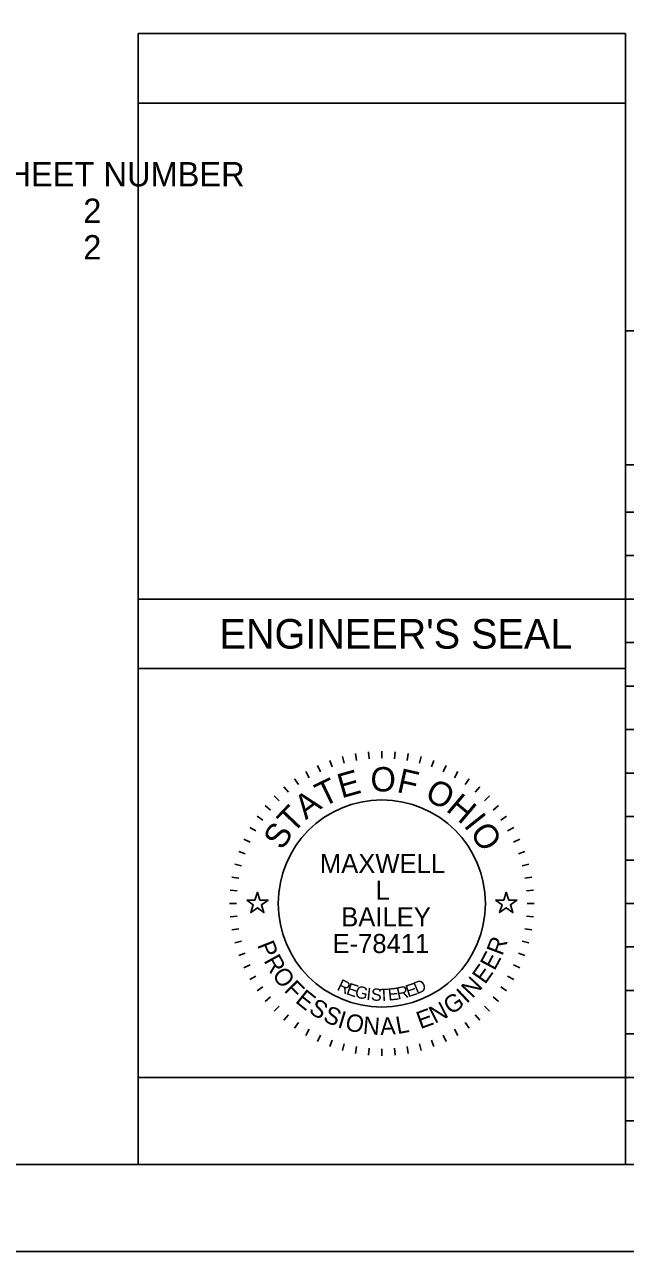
# Model space of a CAD drawing. Extents: x 0 to 34, y 0 to 22.
# Drawn here: x 6.7 to 10.15, y 0 to 7.05 of the extents above; entities that cross this region are included whole.
import ezdxf

# ---------------------------------------------------------------- set-up
doc = ezdxf.new("R2010")
doc.units = 0
for name, color, linetype in [('SH_Border', 7, 'Continuous'), ('SH_Cut_Line', 7, 'Continuous'), ('SH_Data', 7, 'Continuous'), ('SH_Seal', 7, 'Continuous'), ('SH_Text', 7, 'Continuous')]:
    doc.layers.add(name, color=color, linetype=linetype)

msp = doc.modelspace()

# ---------------------------------------------------------------- linework, layer by layer
at = {"layer": 'SH_Border'}
msp.add_lwpolyline([(1.5, 21.5), (33.5, 21.5), (33.5, 0.5), (1.5, 0.5)], close=True, dxfattribs=at)
at = {"layer": 'SH_Cut_Line'}
msp.add_lwpolyline([(0, 0), (34, 0), (34, 22), (0, 22)], close=True, dxfattribs=at)
at = {"layer": 'SH_Data'}
for p, q in [((7.35, 6.6), (10.15, 6.6)), ((10.15, 5.2917), (23.6, 5.2917)), ((10.15, 0.5), (10.15, 5.2917)), ((10.15, 4.5209), (23.6, 4.5209)), ((10.15, 4.25), (21.875, 4.25)), ((10.15, 4), (21.875, 4)), ((10.15, 3.75), (7.35, 3.75)), ((7.35, 3.75), (7.35, 0.5)), ((10.15, 3.75), (21.875, 3.75)), ((10.15, 0.5), (10.15, 3.75)), ((10.15, 3.5), (21.875, 3.5)), ((7.35, 3.35), (10.15, 3.35)), ((10.15, 3.35), (7.35, 3.35)), ((10.15, 3.25), (23.6, 3.25)), ((10.15, 3), (23.6, 3)), ((10.15, 2.75), (23.6, 2.75)), ((10.15, 2.5), (23.6, 2.5)), ((10.15, 2.25), (23.6, 2.25)), ((10.15, 2), (23.6, 2)), ((10.15, 1.75), (23.6, 1.75)), ((10.15, 1.5), (23.6, 1.5)), ((10.15, 1.25), (23.6, 1.25)), ((10.15, 1), (23.6, 1)), ((10.15, 0.75), (23.6, 0.75)), ((10.15, 0.5), (7.35, 0.5))]:
    msp.add_line(p, q, dxfattribs=at)
for points in [[(10.15, 7), (7.35, 7), (7.35, 3.75), (10.15, 3.75)], [(10.15, 3.75), (7.35, 3.75), (7.35, 0.5), (10.15, 0.5)], [(10.15, 0.5), (10.15, 1), (7.35, 1), (7.35, 0.5)]]:
    msp.add_lwpolyline(points, close=True, dxfattribs=at)
at = {"layer": 'SH_Seal'}
for p, q in [((8.4507, 2.8222), (8.4644, 2.7846)), ((8.5235, 2.8452), (8.5339, 2.8065)), ((8.5981, 2.8617), (8.605, 2.8223)), ((8.6737, 2.8717), (8.6772, 2.8318)), ((8.75, 2.875), (8.75, 2.835)), ((8.8263, 2.8717), (8.8228, 2.8318)), ((8.9019, 2.8617), (8.895, 2.8223)), ((8.9765, 2.8452), (8.9661, 2.8065)), ((9.0493, 2.8222), (9.0356, 2.7846)), ((8.3125, 2.7578), (8.3325, 2.7231)), ((8.3802, 2.793), (8.3971, 2.7568)), ((9.1198, 2.793), (9.1029, 2.7568)), ((9.1875, 2.7578), (9.1675, 2.7231)), ((8.2481, 2.7168), (8.2711, 2.684)), ((9.2519, 2.7168), (9.2289, 2.684)), ((8.1313, 2.6187), (8.1596, 2.5904)), ((8.1876, 2.6703), (8.2133, 2.6396)), ((9.3124, 2.6703), (9.2867, 2.6396)), ((9.3687, 2.6187), (9.3404, 2.5904)), ((8.0797, 2.5624), (8.1104, 2.5367)), ((9.4203, 2.5624), (9.3896, 2.5367)), ((8.0332, 2.5019), (8.066, 2.4789)), ((9.4668, 2.5019), (9.434, 2.4789)), ((7.9922, 2.4375), (8.0269, 2.4175)), ((9.5078, 2.4375), (9.4731, 2.4175)), ((7.957, 2.3698), (7.9932, 2.3529)), ((9.543, 2.3698), (9.5068, 2.3529)), ((7.9278, 2.2993), (7.9654, 2.2856)), ((9.5722, 2.2993), (9.5346, 2.2856)), ((7.9048, 2.2265), (7.9435, 2.2161)), ((9.5952, 2.2265), (9.5565, 2.2161)), ((7.8883, 2.1519), (7.9277, 2.145)), ((9.6117, 2.1519), (9.5723, 2.145)), ((7.8783, 2.0763), (7.9182, 2.0728)), ((9.6217, 2.0763), (9.5818, 2.0728)), ((7.875, 2), (7.915, 2)), ((9.625, 2), (9.585, 2)), ((7.8783, 1.9237), (7.9182, 1.9272)), ((9.6217, 1.9237), (9.5818, 1.9272)), ((7.8883, 1.8481), (7.9277, 1.855)), ((9.6117, 1.8481), (9.5723, 1.855)), ((7.9048, 1.7735), (7.9435, 1.7839)), ((9.5952, 1.7735), (9.5565, 1.7839)), ((7.9278, 1.7007), (7.9654, 1.7144)), ((9.5722, 1.7007), (9.5346, 1.7144)), ((7.957, 1.6302), (7.9932, 1.6471)), ((9.543, 1.6302), (9.5068, 1.6471)), ((7.9922, 1.5625), (8.0269, 1.5825)), ((9.5078, 1.5625), (9.4731, 1.5825)), ((8.0332, 1.4981), (8.066, 1.5211)), ((9.4668, 1.4981), (9.434, 1.5211)), ((8.0797, 1.4376), (8.1104, 1.4633)), ((9.4203, 1.4376), (9.3896, 1.4633)), ((8.1313, 1.3813), (8.1596, 1.4096)), ((8.1876, 1.3297), (8.2133, 1.3604)), ((9.3124, 1.3297), (9.2867, 1.3604)), ((9.3687, 1.3813), (9.3404, 1.4096)), ((8.2481, 1.2832), (8.2711, 1.316)), ((8.3125, 1.2422), (8.3325, 1.2769)), ((9.1875, 1.2422), (9.1675, 1.2769)), ((9.2519, 1.2832), (9.2289, 1.316)), ((8.3802, 1.207), (8.3971, 1.2432)), ((8.4507, 1.1778), (8.4644, 1.2154)), ((9.0493, 1.1778), (9.0356, 1.2154)), ((9.1198, 1.207), (9.1029, 1.2432)), ((8.5235, 1.1548), (8.5339, 1.1935)), ((8.5981, 1.1383), (8.605, 1.1777)), ((8.6737, 1.1283), (8.6772, 1.1682)), ((8.75, 1.125), (8.75, 1.165)), ((8.8263, 1.1283), (8.8228, 1.1682)), ((8.9019, 1.1383), (8.895, 1.1777)), ((8.9765, 1.1548), (8.9661, 1.1935))]:
    msp.add_line(p, q, dxfattribs=at)
for points in [[(7.9736, 2.02), (8.0205, 2.02), (8.035, 2.0645), (8.0495, 2.02), (8.0964, 2.02), (8.0585, 1.9924), (8.073, 1.9478), (8.035, 1.9754), (7.997, 1.9478), (8.0115, 1.9924)], [(9.4036, 2.02), (9.4505, 2.02), (9.465, 2.0645), (9.4795, 2.02), (9.5264, 2.02), (9.4885, 1.9924), (9.503, 1.9478), (9.465, 1.9754), (9.427, 1.9478), (9.4415, 1.9924)]]:
    msp.add_lwpolyline(points, close=True, dxfattribs=at)
msp.add_circle((8.75, 2), 0.595, dxfattribs=at)

# ---------------------------------------------------------------- texts
at = {"layer": 'SH_Data'}
msp.add_text("ENGINEER'S SEAL", height=0.17, dxfattribs=at).set_placement((7.8176, 3.465))
at = {"layer": 'SH_Seal'}
for s, height, rotation, p in [('E', 0.14, 15.75706, (8.5184, 2.6038)), ('O', 0.14, 359.78119, (8.6847, 2.6443)), ('F', 0.14, 347.43619, (8.8311, 2.6417)), ('T', 0.14, 25.71674, (8.4116, 2.5518)), ('O', 0.14, 332.25863, (8.9898, 2.6015)), ('A', 0.14, 36.47472, (8.3134, 2.4781)), ('H', 0.14, 319.91363, (9.1132, 2.5361)), ('T', 0.14, 46.4344, (8.2383, 2.3964)), ('I', 0.14, 308.36695, (9.2165, 2.4483)), ('S', 0.14, 57.19238, (8.1781, 2.3014)), ('O', 0.14, 303.14906, (9.2521, 2.4089)), ('P', 0.1, 291.49398, (8.0323, 1.7621)), ('R', 0.1, 69.23216, (9.4419, 1.6954)), ('R', 0.1, 298.73106, (8.069, 1.6717)), ('E', 0.1, 61.99508, (9.3976, 1.6098)), ('O', 0.1, 306.46664, (8.1155, 1.5883)), ('E', 0.1, 54.75801, (9.3433, 1.5314)), ('F', 0.1, 314.7068, (8.1843, 1.4983)), ('R', 0.07, 334.48695, (8.4875, 1.5051)), ('D', 0.07, 23.30524, (8.951, 1.477)), ('N', 0.1, 47.02243, (9.2702, 1.4508)), ('E', 0.1, 321.43929, (8.2478, 1.4348)), ('E', 0.07, 341.03996, (8.5406, 1.4801)), ('G', 0.07, 347.47515, (8.5914, 1.4618)), ('I', 0.07, 353.78581, (8.6591, 1.4468)), ('S', 0.07, 356.89262, (8.6858, 1.4429)), ('T', 0.07, 3.00609, (8.7357, 1.4387)), ('E', 0.07, 6.01169, (8.7889, 1.4412)), ('R', 0.07, 11.91844, (8.8425, 1.4474)), ('E', 0.07, 17.68363, (8.8998, 1.4602)), ('I', 0.1, 43.28703, (9.2368, 1.4214)), ('S', 0.1, 328.67637, (8.3243, 1.3752)), ('N', 0.1, 27.31129, (9.0545, 1.3075)), ('G', 0.1, 35.04687, (9.1481, 1.357)), ('S', 0.1, 335.91345, (8.4064, 1.3266)), ('I', 0.1, 343.15053, (8.4906, 1.2897)), ('O', 0.1, 346.88592, (8.5339, 1.2751)), ('N', 0.1, 355.12608, (8.6388, 1.2517)), ('A', 0.1, 2.86166, (8.7423, 1.2437)), ('L', 0.1, 10.09874, (8.8394, 1.249)), ('E', 0.1, 20.07421, (8.9712, 1.277))]:
    msp.add_text(s, height=height, rotation=rotation, dxfattribs=at).set_placement(p)
for s, p in [('MAXWELL', (8.3941, 2.1749)), ('L', (8.7145, 2.0216)), ('BAILEY', (8.5167, 1.8684)), ('E-78411', (8.4667, 1.7151))]:
    msp.add_text(s, height=0.11, dxfattribs=at).set_placement(p)
at = {"layer": 'SH_Text'}
for s, p in [('SHEET NUMBER', (6.4744, 6.1217)), ('2', (7.0344, 5.9117)), ('2', (7.0344, 5.7017))]:
    msp.add_text(s, height=0.14, dxfattribs=at).set_placement(p)

doc.saveas('drawing.dxf')
